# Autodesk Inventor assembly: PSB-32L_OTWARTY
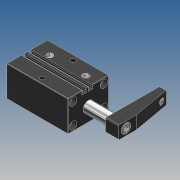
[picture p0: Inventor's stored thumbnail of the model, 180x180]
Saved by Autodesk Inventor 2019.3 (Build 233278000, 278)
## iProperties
Created: 2010-02
Part Number: PSB-32L_OTWARTY
Material: Ogólny
Document SubType Name: Assembly
Designer: CADENGINEERING4
Sending System: PRO/ENGINEER BY PARAMETRIC TECHNOLOGY CORPORATION, 2007170
Preprocessor: PRO/ENGINEER BY PARAMETRIC TECHNOLOGY CORPORATION, 2007170
Title: PSB-32_ASM
Author: Administrator
Revision Number: 1LAST_VERSION
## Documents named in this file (6)
- E:\SERWER_ZAPAS\Pneumatic\PSB PNEUMATIC SWING\PSB-32\PSB-32L_OTWARTY.iam
- E:\SERWER_ZAPAS\Pneumatic\PSB PNEUMATIC SWING\PSB-32\PSB-32BT.ipt
- E:\SERWER_ZAPAS\Pneumatic\PSB PNEUMATIC SWING\PSB-32\PSB-32HSG.ipt
- E:\SERWER_ZAPAS\Pneumatic\PSB PNEUMATIC SWING\PSB-32\PSB-32HG.ipt
- E:\SERWER_ZAPAS\Pneumatic\PSB PNEUMATIC SWING\PSB-32\PSB-32YB.ipt
- E:\SERWER_ZAPAS\Pneumatic\PSB PNEUMATIC SWING\PSB-32\M8X20.ipt
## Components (5 placed, 5 different names)
1. PSB-32BT_0 — Zestawiające:1, Zestawiające:6, Kątowe:1
2. PSB-32HSG_1 — Zestawiające:1, Zestawiające:2, Zestawiające:3, Zestawiające:6
3. PSB-32HG_2
4. PSB-32YB_3 — Zestawiające:2, Zestawiające:3, Zestawiające:4, Zestawiające:5, Kątowe:1
5. M8X20_4 — Zestawiające:4, Zestawiające:5
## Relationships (7: Mate 6, Angle 1)
- Zestawiające:1 [Mate]: PSB-32BT_0 ↔ PSB-32HSG_1
- Zestawiające:2 [Mate]: PSB-32HSG_1 ↔ PSB-32YB_3
- Zestawiające:3 [Mate]: PSB-32HSG_1 ↔ PSB-32YB_3
- Zestawiające:4 [Mate]: PSB-32YB_3 ↔ M8X20_4
- Zestawiające:5 [Mate]: PSB-32YB_3 ↔ M8X20_4
- Zestawiające:6 [Mate]: PSB-32BT_0 ↔ PSB-32HSG_1
- Kątowe:1 [Angle]: PSB-32BT_0 ↔ PSB-32YB_3
